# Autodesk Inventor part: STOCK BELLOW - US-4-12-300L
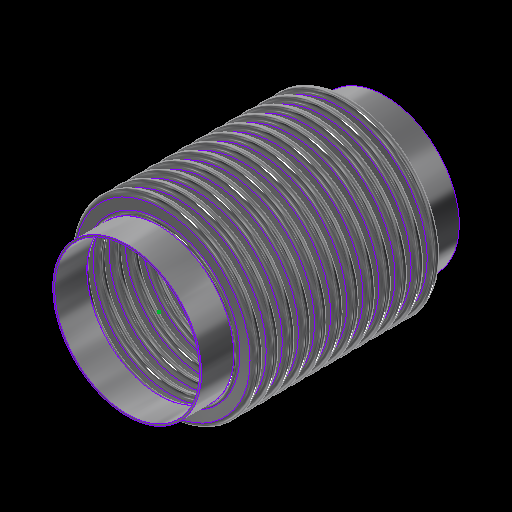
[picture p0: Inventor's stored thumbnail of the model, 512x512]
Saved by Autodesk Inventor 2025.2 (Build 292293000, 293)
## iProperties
Category: 22 GA (0.030 THICK)
RuleStatus: InUse
Created: 2024-01
Part Number: STOCK BELLOW - US-4-12-300L
Project: =STOCK BELLOWS: <Stock Number><SFILL>
Material: ASTM A240-304
Description: =STOCK BELLOWS: <Stock Number>, <SID_> I.D., <SOD_> O.D., <SPLY_> PLY, <Category>, <SNET_CONS> CONS.<PITCH_><STANGENT_> TANGENT<SFILL>
Document SubType Name: Sheet Metal
Designer: GS
Stock Number: U.S-4-12-300L
Surface Area: 3931.55 cm^2
Volume: 297.049 cm^3
Sheet Metal Rule: Default
Appearance: STAINLESS STEEL
Mass: 2393.41 g
Density: 8.05729 g/cm^3
THK: 0.036
ID: 3.500
OD: 4.250
CONS_: 2
PITCH: 0.500
TANGENT: 0.500
BELLOWS_UPSET: 0.000
d79: 1.000
d82: 1.000
d83: 26.000
d84: 24.000
d174: 8
d214: 8
STHK_: 0.030
SID_: 4.500
SOD_: 5.750
SPITCH_: 0.500
STANGENT__: 1.000
SBELLOWS_UPSET_: 0.000
SDIFF_TAN: 1.000
d252: 2
d275: 2
d287: 0.050
d289: 0.500
d290: 0.000
SOD_NECK: 4 5/8
PLY: 1
PSET: 4.178
PBAR: 1.035
COUNTER: 1.500
NET_TUBE: 3.071
CONS: 2
S_CONS: 0
NET_CONS: 2
ID_M: 88.90 mm
OD_M: 107.95 mm
THK_M: 0.91 mm
ID_U: 3.500 in
OD_U: 4.250 in
THK_U: 0.036 in
TANGENT2: 0.500
TAN_TO_TAN: 1.000 in
d80: 2.571
d81: 10
SID: 2.375
SCONS_: 12
SPITCH: 0.250
STANGENT_: 1.000
SBELLOWS_UPSET: 0.000
SNET_CONS: 12
SS_CONS: 0
SCONS: 8
d190: 8
d191: 1
d192: 1
d193: 8
d194: 0
SIZE: 4.00
PRESSURE: 300
d230: 8
STANGENT: 4.000
SPLY_: 2
d233: 8
d234: 0
d263: 2
d265: 1
d268: 2
d269: 0
d286: 2
d288: 1
d291: 2
d292: 0
SREROLL: 0.750
BLETP: 1.000 ul
PRES_Copy: 85
MATTABLE: 20 GA (0.036 THICK)
PART_NUMBER: U.S-4-12-300L
PITCH_: =, <SPITCH_> PITCH,
CFILL: .
SFILL: .
MESH: ,
COMP: 1.16
EXT: 0.58
LAT: 0.45
ANG: 573
ASR: 1715
LSR: 1877
ANSR: 98
PRES: 300
COMPM: 11.6
EXTM: 5.8
LATM: 4.50
ASRM: 300.348
PRESM: 20.684
LSRM: 328.719
ANSRM: 17.163
TEMPMIN: 20
TEMPMAX: 800
TEMPMINM: -7
TEMPMAXM: 427
WEIGHTM: 2.393
WEIGHT: 5.277
Author: GS
Keywords: 20 GA (0.036 THICK)
Comments: =STOCK BELLOW - <STOCK NUMBER>
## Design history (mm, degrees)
sketch "Sketch2"
  geometry: L1 (0, -177.245)-(0, 562.856) reference; L2 (45.364, 0)-(44.45, 0); L3 (48.082, -2.718)-(50.343, -2.718); L4 (48.082, -3.632)-(50.343, -3.632); L5 (50.343, -9.982)-(48.082, -9.982); L6 (50.343, -9.068)-(48.082, -9.068); L7 (45.364, -12.7)-(44.45, -12.7); L8 (48.082, 0)-(48.082, -12.7); L9 (50.343, -6.35)-(53.975, -6.35); L10 (44.45, 0)-(44.45, -12.7); L11 (20.376, 102.841)-(20.376, 101.926); L12 (58.262, 457.127)-(58.262, 349.177); L13 (58.262, 444.427)-(58.262, 336.477); L14 (93.133, -58.817)-(93.133, -71.517); L15 (118.746, -66.401)-(118.746, -66.401); L16 (50.343, -9.068)-(50.343, -9.982); L17 (48.082, -9.068)-(48.082, -9.982); L18 (48.082, -9.525)-(50.343, -9.525); L19 (53.975, 0)-(53.975, -12.7); L20 (-50.343, -9.068)-(-50.343, -9.982); L21 (-50.343, -2.718)-(-48.082, -2.718); L22 (-50.343, -3.632)-(-48.082, -3.632); L23 (-48.082, -9.068)-(-50.343, -9.068); L24 (-50.343, -9.525)-(-48.082, -9.525); L25 (-48.082, -9.982)-(-50.343, -9.982); L26 (-48.082, -9.068)-(-48.082, -9.982); L27 (-44.45, 0.653)-(-44.45, -12.047); L28 (-48.082, -6.35)-(-44.45, -6.35); L29 (-50.343, 0.653)-(-50.343, -12.7); L30 (-53.061, 0)-(-53.975, 0); L31 (-53.975, 0)-(-53.975, -12.7); L32 (-53.061, -12.7)-(-53.975, -12.7); A1 r 2.718 centre (48.082, 0) between (45.364, 0) and (48.082, -2.718); A2 r 3.632 centre (48.082, 0) between (44.45, 0) and (48.082, -3.632); A3 r 3.632 centre (50.343, -6.35) between (50.343, -9.982) and (50.343, -2.718); A4 r 2.718 centre (50.343, -6.35) between (50.343, -9.068) and (50.343, -3.632); A5 r 2.718 centre (48.082, -12.7) between (48.082, -9.982) and (45.364, -12.7); A6 r 3.632 centre (48.082, -12.7) between (48.082, -9.068) and (44.45, -12.7); A7 r 3.175 centre (50.343, -6.35) between (50.343, -9.525) and (53.518, -6.35); A8 r 3.175 centre (48.082, -12.7) between (48.082, -9.525) and (44.907, -12.7); A9 r 2.718 centre (-50.343, -12.7) between (-50.343, -9.982) and (-53.061, -12.7); A10 r 2.718 centre (-48.082, -6.35) between (-48.082, -9.068) and (-48.082, -3.632); A11 r 3.175 centre (-48.082, -6.35) between (-48.082, -9.525) and (-44.907, -6.35); A12 r 3.632 centre (-48.082, -6.35) between (-48.082, -9.982) and (-48.082, -2.718); A13 r 3.175 centre (-50.343, -12.7) between (-50.343, -9.525) and (-53.518, -12.7); A14 r 3.632 centre (-50.343, -12.7) between (-50.343, -9.068) and (-53.975, -12.7); A15 r 2.718 centre (-50.343, 0) between (-53.061, 0) and (-50.343, -2.718); A16 r 3.632 centre (-50.343, 0) between (-53.975, 0) and (-50.343, -3.632); 10 further points
  constraints: 62 end point, 38 point on circle, 20 tangent, 16 centre point, 12 parallel, 9 midpoint, 7 vertical, 6 coincident, 6 concentric, 6 point on line, 4 equal radius, 4 perpendicular, 3 horizontal, 1 collinear, 1 horizontal alignment, 10 other
  dimensions: "THK" = 0.9144 distance of L11.start L11.end; "ID" = 88.9 distance of L11.end point (20.376, 13.026); "OD" = 107.95 distance of L12.start L12.end; "PITCH" = 12.7 distance of L12.start L13.start; "TANGENT" = 12.7 distance of L14.start L14.end; "BELLOWS_UPSET" = 0 distance of L15.start L15.end; "d43" = 88.9 diameter of L10 L1 (= ID); "d44" = 107.95 diameter of L9.end L1 (= OD); "d45" = 0.9144 distance between parallel lines of L5 L6 (computed from THK, PLY); "d46" = 3.6322 radius of A3 (computed from PITCH, THK, PLY); "UPSET_PITCH" = 12.7 distance of L2.end L7.end (derived); "SIDEWALL_ANGLE" = 360 deg dimension on L3 L9 (derived); "CON_GAP" = 5.4356 distance of point (48.082, -9.068) point (48.082, -3.632) (derived); "TAN1" = 4.98728 dimension on A8 (derived); "TAN2" = 4.98728 dimension on A7 (derived); "LEG1" = 2.2606 distance of L18.start L18.end (derived); "d278" = 0.9144 distance between parallel lines of L25 L23 (derived); "d279" = 3.6322 radius of A12 (derived); "d280" = 12.7 distance of L30.end L31.end (derived); "d281" = 360 deg dimension on L21 L28 (derived); "d282" = 5.4356 distance of point (-50.343, -9.068) point (-50.343, -3.632) (derived); "d283" = 4.98728 dimension on A13 (derived); "d284" = 4.98728 dimension on A11 (derived); "d285" = 2.2606 distance of L24.start L24.end (derived); "d293" = 88.9 diameter of L27 L1 (derived); "d294" = 107.95 diameter of L31 L1 (derived)
  node "Sketch Rectangular Pattern1" dims "d31" = 25.4, "ID" = 88.9
  node "Sketch Rectangular Pattern2" dims "d39" = 25.4, "PITCH" = 12.7
revolve "CONS" stored, may be unused: angle "d48" = 90 deg
node "BELLOW MIDPLANE"
pattern_linear "Rectangular Pattern2" dims "d52" = 12.7 (= UPSET_PITCH)
sketch "Sketch5"
  geometry: C1 r 45.364 at (0, 0) reference; C2 r 44.45 at (0, 0) reference
extrude "TANGENT" new body sketch "Sketch5" distance "d53" = 12.7 (= TANGENT); taper "d54" = 0 deg
revolve "SAMETAN" stored, may be unused: angle "d65" = 90 deg
revolve "DIFFTAN" stored, may be unused: angle "d70" = 90 deg
sketch "Sketch9"
  geometry: L1 (53.319, 0)-(-53.319, 0) reference; L2 (0, -17.78)-(0, 17.78) reference; L3 (38.085, 0)-(-38.085, 0); L4 (38.085, -11.906)-(38.085, 11.906); L5 (25.385, -11.906)-(25.385, 11.906); L6 (13.15, 11.906)-(13.15, -11.906); L7 (-25.385, -11.906)-(-25.385, 11.906); L8 (-38.085, -11.906)-(-38.085, 11.906); L9 (37.291, -11.906)-(37.291, 11.906); L10 (38.085, -11.906)-(37.291, -11.906); L11 (38.085, 11.906)-(37.291, 11.906); L12 (13.546, 11.906)-(12.753, 11.906); L13 (12.753, 11.906)-(12.753, -11.906); L14 (12.753, -11.906)-(13.546, -11.906); L15 (13.546, -11.906)-(13.546, 11.906); L16 (-13.546, 11.906)-(-13.546, -11.906); L17 (-13.15, 11.906)-(-13.15, -11.906); L18 (-13.546, -11.906)-(-12.753, -11.906); L19 (-12.753, -11.906)-(-12.753, 11.906); L20 (-12.753, 11.906)-(-13.546, 11.906); L21 (-38.085, -11.906)-(-37.291, -11.906); L22 (-37.291, -11.906)-(-37.291, 11.906); L23 (-37.291, 11.906)-(-38.085, 11.906); L24 (-38.085, 11.906)-(-38.085, -11.906); L25 (38.085, -0.397)-(-38.085, -0.397); L26 (-38.085, -0.397)-(-38.085, 0.397); L27 (-38.085, 0.397)-(38.085, 0.397); L28 (38.085, 0.397)-(38.085, -0.397); L29 (-38.085, 11.906)-(38.085, 11.906); L30 (38.085, 11.906)-(38.085, 12.7); L31 (38.085, 12.7)-(-38.085, 12.7); L32 (-38.085, 12.7)-(-38.085, 11.906); L33 (38.085, -11.906)-(-38.085, -11.906); L34 (-38.085, -11.906)-(-38.085, -12.7); L35 (-38.085, -12.7)-(38.085, -12.7); L36 (38.085, -12.7)-(38.085, -11.906); 30 further points
  constraints: 68 end point, 13 midpoint, 13 parallel, 8 horizontal, 7 perpendicular, 6 equal length, 3 point on line, 2 vertical, 14 other
  dimensions: "d115" = 23.8125 distance of L4.start L4.end (derived); "d116" = 12.7 distance between parallel lines of L4 L5 (derived); "d117" = 12.23516 distance between parallel lines of L5 L6 (derived); "d125" = 38.53427 distance between parallel lines of L7 L6 (derived); "d127" = 12.7 distance between parallel lines of L8 L7 (derived); "d128" = 24.93516 distance between parallel lines of L6 L4 (derived); "d130" = 76.16943 distance between parallel lines of L8 L4 (derived); "RULER_THK" = 0.79375 distance between parallel lines of L4 L9; "d135" = 0.79375 distance of L13.end L14.end (derived); "d138" = 26.29911 distance of L13.end L16.end (derived); "d143" = 0.79375 distance of L22.end L8.end (derived); "d144" = 0.79375 distance between parallel lines of L27 L25 (derived)
extrude "RULER" join sketch "Sketch9" distance "d149" = 0.79375 (derived); taper "d150" = 0 deg
extrude "BARS" join sketch "Sketch9" distance "d151" = 0.79375 (derived); taper "d152" = 0 deg
pattern_linear "Rectangular Pattern4" dims "d155" = 26.29911 (derived)
sketch "Sketch13"
  geometry: L1 (93.149, -52.467)-(93.149, -77.867); L2 (58.674, 0)-(57.15, 0); L3 (58.674, -12.7)-(57.15, -12.7); L4 (69.088, -10.287)-(61.087, -10.287); L5 (69.088, -8.763)-(61.087, -8.763); L6 (69.088, -6.35)-(73.025, -6.35); L7 (61.087, -2.413)-(69.088, -2.413); L8 (61.087, 0)-(61.087, -12.7); L9 (57.15, 0)-(57.15, -12.7); L10 (58.254, -350.381)-(58.254, -496.431); L11 (58.254, -363.081)-(58.254, -509.131); L12 (58.254, -388.481)-(58.254, -534.531); L13 (58.254, -401.181)-(58.254, -547.231); L14 (58.254, -413.881)-(58.254, -559.931); L15 (58.254, -426.581)-(58.254, -572.631); L16 (58.254, -439.281)-(58.254, -585.331); L17 (58.254, -375.781)-(58.254, -521.831); L18 (20.376, 102.688)-(20.376, 101.926); L19 (61.087, -3.937)-(69.088, -3.937); L20 (0, -722.935)-(0, 240.292) reference; L21 (-23.752, 0)-(142.514, 0) reference; A1 r 2.413 centre (61.087, 0) between (58.674, 0) and (61.087, -2.413); A2 r 2.413 centre (61.087, -12.7) between (61.087, -10.287) and (58.674, -12.7); A3 r 3.937 centre (61.087, -12.7) between (61.087, -8.763) and (57.15, -12.7); A4 r 2.413 centre (69.088, -6.35) between (69.088, -8.763) and (69.088, -3.937); A5 r 3.937 centre (69.088, -6.35) between (69.088, -10.287) and (69.088, -2.413); A6 r 3.937 centre (61.087, 0) between (57.15, 0) and (61.087, -3.937); 6 further points; 1 other entity
  constraints: 38 end point, 15 point on circle, 9 tangent, 6 centre point, 6 parallel, 5 vertical alignment, 4 point on line, 4 vertical, 3 coincident, 3 concentric, 2 collinear, 2 equal radius, 1 horizontal, 1 perpendicular, 23 other
  dimensions: "SBELLOWS_UPSET_" = 0 distance of point (118.762, -66.401) point (118.762, -66.401); "STOTAL_THK_BELLOW__" = 1.524 distance between parallel lines of L4 L5 (derived); "d224" = 3.937 radius of A5 (derived); "d225" = 12.7 distance of L2.end L3.end (derived); "SSIDEWALL_ANGLE_" = 360 deg dimension on L7 L6 (derived); "SSCON_GAP_" = 4.826 distance of point (61.087, -8.763) point (61.087, -3.937) (derived); "d235" = 114.3 diameter of L9 L20 (derived); "d236" = 146.05 diameter of L6.end L20 (derived)
  node "Sketch Rectangular Pattern4" dims "d228" = 25.4
  node "Sketch Rectangular Pattern5" dims "d229" = 25.4
revolve "SBELLOW" stored, may be unused: angle "d197" = 90 deg
pattern_linear "Rectangular Pattern5" dims "d204" = 12.7 (derived)
revolve "STANGENT" stored, may be unused: angle "d240" = 90 deg
revolve "SSAMETAN" stored, may be unused: angle "d241" = 90 deg
revolve "SDIFFTAN" stored, may be unused: angle "d246" = 90 deg
revolve "INVCON" stored, may be unused: angle "d295" = 90 deg
pattern_linear "Rectangular Pattern6" dims "d298" = 12.7 (derived)
revolve "INVTANGENT" stored, may be unused: angle "d302" = 90 deg
revolve "INVSAMETAN" stored, may be unused: angle "d307" = 90 deg
revolve "INVDIFFTAN" stored, may be unused: angle "d312" = 90 deg
sketch "ID BELLOW MOUNT CALC"
  geometry: L1 (44.45, 0)-(38.1, 0); L2 (38.1, 0)-(38.1, 12.7); L3 (38.1, 12.7)-(44.45, 12.7); L4 (44.45, 12.7)-(44.45, 0); L5 (36.513, 12.7)-(35.598, 12.7); L6 (35.598, 12.7)-(35.598, 0); L7 (35.598, 0)-(36.513, 0); L8 (36.513, 0)-(36.513, 12.7); L9 (0, -2.54)-(0, 15.24) reference; L10 (-8.89, 0)-(53.34, 0) reference; 1 further point
  constraints: 16 end point, 5 parallel, 2 collinear, 2 horizontal, 2 perpendicular
  dimensions: "d314" = 12.7 distance of L5.end L6.end (derived); "d315" = 0.9144 distance of L5.start L5.end (derived); "IG" = 1.5875 distance between parallel lines of L2 L8; "PIPE_OD" = 88.9 diameter of L4 L9; "PIPE_WALL" = 6.35 distance of L2.end L3.end; "ID_MT_BELLOW" = 71.1962 diameter of L6 L9 (derived)
revolve "CFILL" stored, may be unused: angle "d320" = 90 deg
pattern_linear "Rectangular Pattern7" dims "d323" = 12.7 (derived)
revolve "SFILL" stored, may be unused: angle "d324" = 90 deg
pattern_linear "Rectangular Pattern8" dims "d327" = 12.7 (derived)
node "STOCK BELLOW MIDPLANE"
node "BELLOW"
sketch "Sketch6"
  geometry: L1 (-12.7, 45.364)-(0, 45.364); L2 (0, 45.364)-(0, 44.45); L3 (0, 44.45)-(-12.7, 44.45); L4 (-12.7, 44.45)-(-12.7, 45.364); L5 (10.16, 0)-(-60.96, 0) reference; L6 (-38.1, -89.422)-(-38.1, 153.44) reference; 1 further point
  constraints: 8 end point, 2 parallel, 1 horizontal, 1 perpendicular
  dimensions: "d61" = 12.7 distance of L2.end L3.end (derived); "d62" = 0.9144 distance of L1.end L2.end (derived); "d63" = 88.9 diameter of L3 L5 (derived); "d64" = 25.4 distance between parallel lines of L4 L6 (derived)
sketch "Sketch12"
  geometry: 1 further point
sketch "Sketch14"
  geometry: L1 (-25.4, 58.674)-(0, 58.674); L2 (0, 58.674)-(0, 57.15); L3 (0, 57.15)-(-25.4, 57.15); L4 (-25.4, 57.15)-(-25.4, 58.674); L5 (5.08, 0)-(-30.48, 0) reference; L6 (0, -11.735)-(0, 70.409) reference; 1 further point
  constraints: 8 end point, 2 parallel, 1 collinear, 1 horizontal, 1 perpendicular
  dimensions: "d237" = 1.524 distance of L3.end L1.start (derived); "d238" = 114.3 diameter of L3 L5 (derived); "d239" = 25.4 distance of L1.start L1.end (derived); "SOD_NECK" = 117.348 diameter of L1 L5 (derived)
sketch "Sketch15"
  geometry: L1 (-11.735, 0)-(70.409, 0) reference; L2 (57.15, -152.4)-(58.674, -152.4); L3 (58.674, -152.4)-(58.674, -177.8); L4 (58.674, -177.8)-(57.15, -177.8); L5 (57.15, -177.8)-(57.15, -152.4); L6 (0, -215.9)-(0, 50.8) reference; 1 further point
  constraints: 8 end point, 2 parallel, 1 horizontal, 1 perpendicular
  dimensions: "d205" = 25.4 distance of L4.end L2.start (derived); "d206" = 1.524 distance of L3.end L4.end (derived); "d207" = 114.3 diameter of L5 L6 (derived); "d208" = 152.4 distance between parallel lines of L1 L2 (derived)
node "TANGENT_"
node "SAME_TAN"
sketch "Sketch8"
  geometry: L1 (45.364, -25.4)-(44.45, -25.4); L2 (44.45, -25.4)-(44.45, -38.1); L3 (44.45, -38.1)-(45.364, -38.1); L4 (45.364, -38.1)-(45.364, -25.4); L5 (0, -48.26)-(0, 22.86) reference; L6 (-89.422, 0)-(153.44, 0) reference; 1 further point
  constraints: 8 end point, 2 parallel, 1 horizontal, 1 perpendicular
  dimensions: "d66" = 88.9 diameter of L2 L5 (derived); "TOTAL_THK_BELLOW" = 0.9144 distance of L2.end L3.end (derived); "d68" = 25.4 distance between parallel lines of L1 L6 (derived); "d69" = 12.7 distance of L1.end L2.end (derived)
node "DIFF_TAN"
node "Sketch Rectangular Pattern3" dims "d138" = 26.29911 (derived), "d141" = 25.4
node "SBELLOW_"
node "STANGENT_"
node "SSAME_TAN"
sketch "Sketch16"
  geometry: L1 (58.674, -152.4)-(57.15, -152.4); L2 (57.15, -152.4)-(57.15, -177.8); L3 (57.15, -177.8)-(58.674, -177.8); L4 (58.674, -177.8)-(58.674, -152.4); L5 (0, -215.9)-(0, 50.8) reference; L6 (-11.735, 0)-(70.409, 0) reference; 1 further point
  constraints: 8 end point, 2 parallel, 1 horizontal, 1 perpendicular
  dimensions: "SDIFF_TAN" = 25.4 distance of L3.end L1.start; "d243" = 1.524 distance of L2.end L3.end (derived); "d244" = 152.4 distance between parallel lines of L1 L6 (derived); "d245" = 114.3 diameter of L2 L5 (derived)
node "SDIFF_TAN"
body "Solid15"
sketch "Sketch17"
  geometry: L1 (53.975, 12.7)-(53.061, 12.7); L2 (53.061, 12.7)-(53.061, 0); L3 (53.061, 0)-(53.975, 0); L4 (53.975, 0)-(53.975, 12.7); L5 (0, -2.54)-(0, 15.24) reference; L6 (-10.795, 0)-(64.77, 0) reference; 2 further points
  constraints: 8 end point, 2 parallel, 1 horizontal, 1 midpoint, 1 perpendicular, 1 point on line
  dimensions: "INVTANGENT" = 12.7 distance of L3.end L1.start (derived); "d300" = 0.9144 distance of L1.start L1.end (derived); "d301" = 107.95 diameter of L4 L5 (derived)
body "Solid16"
sketch "Sketch18"
  geometry: L1 (53.975, -25.4)-(53.061, -25.4); L2 (53.061, -25.4)-(53.061, -38.1); L3 (53.061, -38.1)-(53.975, -38.1); L4 (53.975, -38.1)-(53.975, -25.4); L5 (-10.795, 0)-(64.77, 0) reference; L6 (0, -48.26)-(0, 22.86) reference; 1 further point
  constraints: 8 end point, 2 parallel, 1 horizontal, 1 perpendicular
  dimensions: "d303" = 25.4 distance between parallel lines of L1 L5 (derived); "d304" = 12.7 distance of L3.end L1.start (derived); "d305" = 0.9144 distance of L2.end L3.end (derived); "d306" = 107.95 diameter of L4 L6 (derived)
body "Solid17"
sketch "Sketch19"
  geometry: L1 (53.975, -25.4)-(53.061, -25.4); L2 (53.061, -25.4)-(53.061, -38.1); L3 (53.061, -38.1)-(53.975, -38.1); L4 (53.975, -38.1)-(53.975, -25.4); L5 (0, -48.26)-(0, 22.86) reference; L6 (-10.795, 0)-(64.77, 0) reference; 1 further point
  constraints: 8 end point, 2 parallel, 1 horizontal, 1 perpendicular
  dimensions: "d308" = 12.7 distance of L1.end L2.end (derived); "d309" = 107.95 diameter of L4 L5 (derived); "d310" = 0.9144 distance of L2.end L3.end (derived); "d311" = 25.4 distance between parallel lines of L1 L6 (derived)
body "Solid18"
body "Solid19"
body "Solid20"
other parameters: "BMPL" = -76.2, "PSET" = 106.1212 (computed from OD, THK, PLY) [user parameter], "PBAR" = 26.29911 (= 0.570796 x PITCH + OD - ID) [user parameter; used in 1 equation term], "COUNTER" = 15 [user parameter], "NET_TUBE" = 77.99823 (computed from CONS_, PBAR, TANGENT) [user parameter], "S_CONS" = 0 [user parameter; used in 1 equation term], "ID_M" = 88.9 (= ID) [user parameter], "OD_M" = 107.95 (= OD) [user parameter], "THK_M" = 0.9144 (= THK) [user parameter], "ID_U" = 88.9 (= ID) [user parameter], "OD_U" = 107.95 (= OD) [user parameter], "THK_U" = 0.9144 (= THK) [user parameter], "D_UNITS" = 0 [user parameter], "TANGENT2" = 12.7 [user parameter], "TAN_TO_TAN" = 25.4 [user parameter], "OD_NECK" = 90.7288 [user parameter], "d79" = 25.4, "d80" = 65.29823 [user parameter], "d82" = 25.4, "d83" = 660.4, "d84" = 609.6, "sa_0" = 4, "FRAME_THK" = 0.79375 [user parameter], "CON_FLAT" = 12.23516 [user parameter], "SID" = 60.325 [user parameter], "SPITCH" = 6.35 [user parameter], "STANGENT_" = 25.4 [user parameter], "SBELLOWS_UPSET" = 0 [user parameter], "SS_CONS" = 0 [user parameter], "STAN_TO_TAN_" = 152.4 [user parameter], "d100" = 1.524 [user parameter], "d191" = 25.4 [user parameter], "d194" = 0 [user parameter], "STANGENT" = 101.6 [user parameter], "d234" = 0 [user parameter], "SUPSET_PITCH_" = 12.7 [user parameter], "d269" = 0 [user parameter], "d287" = 1.27, "d289" = 12.7, "d290" = 0, "d292" = 0 [user parameter], "Thickness" = 3.048 (derived), "KFactor" = 4.4, "BendRadius" = 3.048 (derived), "BendReliefWidth" = 3.048 (derived), "BendReliefDepth" = 1.524 (derived), "CornerReliefSize" = 12.192 (derived), "SeamGap" = 0.00508, "MinimumRemnant" = 6.096 (derived), "TransitionRadius" = 3.048 (derived), "JacobiRadiusSize" = 3.048 (derived), "GapSize" = 3.048 (derived), "SREROLL" = 19.05 [user parameter], "CUR_STK_PITCH" = 12.7 [user parameter], "d328" = -76.2 (derived), "ASR" = 17150 [user parameter], "LSR" = 18770 [user parameter], "BLETP" = 1 [user parameter], "ASRM" = 3003.4795 [user parameter], "PRESM" = 206.83949 [user parameter], "LSRM" = 3287.1901 [user parameter], "ANSRM" = 171.6274 [user parameter], "TEMPMIN" = 2664.83333 [user parameter], "TEMPMAX" = 6998.16667 [user parameter], "TEMPMINM" = 2664.83333 [user parameter], "TEMPMAXM" = 6998.16667 [user parameter], "WEIGHT" = 23.9341 [user parameter], "WEIGHTM" = 0.02393 [user parameter]
